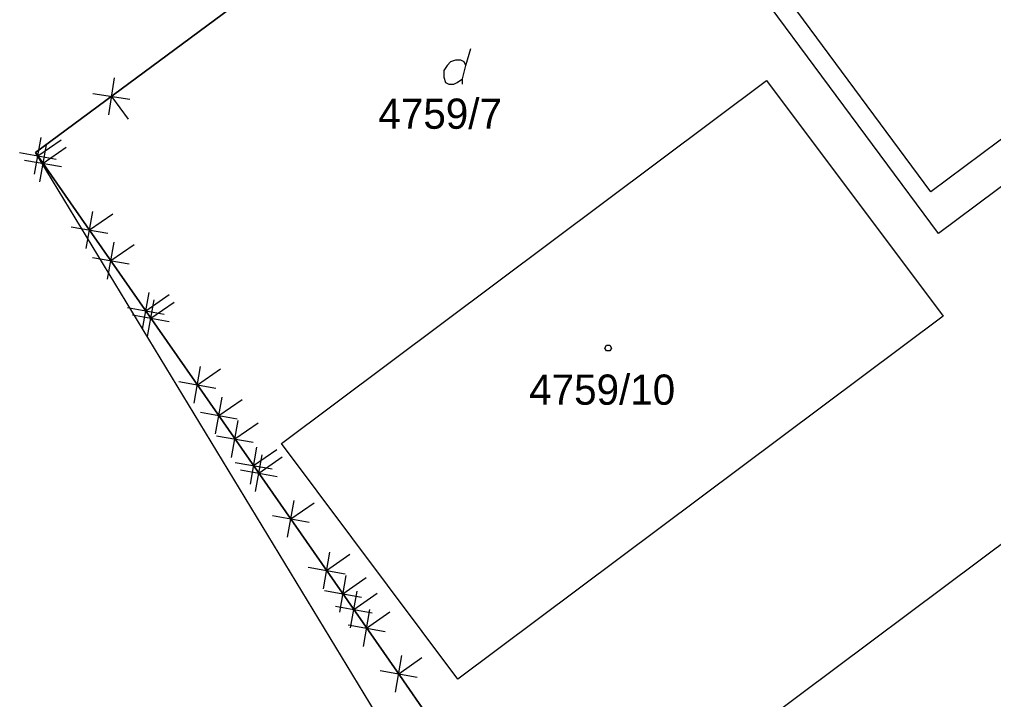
# Model space of a CAD drawing. Extents: x -266179 to -264727, y -1243225 to -1241702.
# Drawn here: x -265653.7 to -265602.1, y -1243026.3 to -1242990.2 of the extents above; entities that cross this region are included whole.
import ezdxf

# ---------------------------------------------------------------- set-up
doc = ezdxf.new("R2010")
doc.units = 0
doc.layers.add('Vrstva 1', color=7, linetype='Continuous')
doc.layers.add('Vrstva 21', color=7, linetype='Continuous')

msp = doc.modelspace()

# ---------------------------------------------------------------- linework, layer by layer
at = {"layer": 'Vrstva 1'}
for p, q in [((-265566.78, -1242970.48), (-265605.43, -1242999.37)), ((-265652.86, -1242997.29), (-265624.02, -1242975.93)), ((-265605.04, -1243001.58), (-265624.02, -1242975.93)), ((-265605.43, -1242999.37), (-265612.83, -1242989.37)), ((-265630.07, -1242992.67), (-265629.8, -1242991.77)), ((-265639.84, -1243012.7), (-265614.14, -1242993.47)), ((-265614.14, -1242993.47), (-265604.79, -1243005.96)), ((-265649.88, -1243001.57), (-265652.86, -1242997.29)), ((-265631.74, -1243032.06), (-265652.86, -1242997.29)), ((-265599.44, -1242997.39), (-265605.04, -1243001.58)), ((-265643.89, -1243010.17), (-265649.88, -1243001.57)), ((-265604.79, -1243005.96), (-265630.5, -1243025.19)), ((-265640.3, -1243015.33), (-265643.89, -1243010.17)), ((-265630.5, -1243025.19), (-265639.84, -1243012.7)), ((-265633.72, -1243024.77), (-265640.3, -1243015.33)), ((-265623.61, -1243034.4), (-265597.9, -1243015.17)), ((-265630.77, -1243029.01), (-265633.72, -1243024.77))]:
    msp.add_line(p, q, dxfattribs=at)
msp.add_lwpolyline([(-265630.25, -1242993.66), (-265630.25, -1242993.39), (-265630.07, -1242992.67), (-265630.16, -1242992.49), (-265630.34, -1242992.4), (-265630.61, -1242992.4), (-265630.88, -1242992.49), (-265631.06, -1242992.67), (-265631.24, -1242992.94), (-265631.24, -1242993.3), (-265631.15, -1242993.57), (-265630.97, -1242993.66), (-265630.7, -1242993.66), (-265630.52, -1242993.57), (-265630.25, -1242993.39)], dxfattribs=at)
msp.add_lwpolyline([(-265622.44, -1243007.5), (-265622.35, -1243007.65), (-265622.44, -1243007.8), (-265622.62, -1243007.8), (-265622.71, -1243007.65), (-265622.62, -1243007.5)], close=True, dxfattribs=at)
at = {"layer": 'Vrstva 21'}
for p, q in [((-265652.86, -1242997.29), (-265624.02, -1242975.93)), ((-265624.02, -1242975.93), (-265652.86, -1242997.29)), ((-265648.697, -1242993.333), (-265648.99, -1242995.291)), ((-265649.823, -1242994.166), (-265647.864, -1242994.459)), ((-265648.843, -1242994.312), (-265647.951, -1242995.518)), ((-265652.912, -1242998.441), (-265652.563, -1242996.492)), ((-265652.737, -1242997.467), (-265651.506, -1242996.61)), ((-265653.711, -1242997.292), (-265651.763, -1242997.641)), ((-265649.88, -1243001.57), (-265652.86, -1242997.29)), ((-265652.86, -1242997.29), (-265649.88, -1243001.57)), ((-265652.637, -1242998.835), (-265652.288, -1242996.886)), ((-265652.462, -1242997.861), (-265651.231, -1242997.004)), ((-265653.437, -1242997.686), (-265651.488, -1242998.035)), ((-265650.177, -1243002.368), (-265649.828, -1243000.419)), ((-265650.003, -1243001.393), (-265648.772, -1243000.536)), ((-265650.977, -1243001.219), (-265649.029, -1243001.568)), ((-265643.89, -1243010.17), (-265649.88, -1243001.57)), ((-265649.88, -1243001.57), (-265643.89, -1243010.17)), ((-265649.043, -1243003.992), (-265648.694, -1243002.043)), ((-265648.868, -1243003.018), (-265647.637, -1243002.161)), ((-265649.843, -1243002.843), (-265647.894, -1243003.192)), ((-265647.196, -1243006.647), (-265646.847, -1243004.698)), ((-265647.022, -1243005.672), (-265645.791, -1243004.815)), ((-265647.996, -1243005.498), (-265646.047, -1243005.847)), ((-265646.923, -1243007.042), (-265646.574, -1243005.093)), ((-265646.748, -1243006.068), (-265645.517, -1243005.211)), ((-265647.723, -1243005.893), (-265645.774, -1243006.242)), ((-265644.464, -1243010.575), (-265644.115, -1243008.626)), ((-265644.289, -1243009.6), (-265643.058, -1243008.743)), ((-265645.263, -1243009.426), (-265643.315, -1243009.775)), ((-265640.3, -1243015.33), (-265643.89, -1243010.17)), ((-265643.89, -1243010.17), (-265640.3, -1243015.33)), ((-265643.329, -1243012.199), (-265642.98, -1243010.25)), ((-265643.154, -1243011.225), (-265641.923, -1243010.368)), ((-265644.129, -1243011.05), (-265642.18, -1243011.399)), ((-265642.473, -1243013.44), (-265642.126, -1243011.491)), ((-265642.299, -1243012.466), (-265641.069, -1243011.607)), ((-265643.274, -1243012.292), (-265641.325, -1243012.639)), ((-265641.482, -1243014.854), (-265641.133, -1243012.905)), ((-265641.308, -1243013.879), (-265640.077, -1243013.022)), ((-265641.21, -1243015.25), (-265640.861, -1243013.301)), ((-265642.282, -1243013.705), (-265640.333, -1243014.054)), ((-265641.036, -1243014.275), (-265639.805, -1243013.418)), ((-265642.01, -1243014.101), (-265640.061, -1243014.45)), ((-265633.72, -1243024.77), (-265640.3, -1243015.33)), ((-265640.3, -1243015.33), (-265633.72, -1243024.77)), ((-265639.513, -1243017.672), (-265639.164, -1243015.724)), ((-265639.338, -1243016.698), (-265638.107, -1243015.841)), ((-265640.313, -1243016.523), (-265638.364, -1243016.872)), ((-265637.616, -1243020.408), (-265637.269, -1243018.459)), ((-265637.443, -1243019.433), (-265636.213, -1243018.575)), ((-265638.417, -1243019.26), (-265636.468, -1243019.607)), ((-265636.751, -1243021.641), (-265636.404, -1243019.692)), ((-265636.577, -1243020.667), (-265635.347, -1243019.808)), ((-265637.552, -1243020.493), (-265635.603, -1243020.84)), ((-265636.173, -1243022.473), (-265635.824, -1243020.524)), ((-265635.999, -1243021.498), (-265634.768, -1243020.641)), ((-265636.973, -1243021.324), (-265635.024, -1243021.673)), ((-265635.496, -1243023.457), (-265635.147, -1243021.508)), ((-265635.322, -1243022.482), (-265634.091, -1243021.625)), ((-265636.296, -1243022.308), (-265634.347, -1243022.657)), ((-265633.799, -1243025.879), (-265633.45, -1243023.93)), ((-265633.624, -1243024.905), (-265632.393, -1243024.048)), ((-265634.599, -1243024.73), (-265632.65, -1243025.079)), ((-265630.77, -1243029.01), (-265633.72, -1243024.77)), ((-265633.72, -1243024.77), (-265630.77, -1243029.01))]:
    msp.add_line(p, q, dxfattribs=at)

# ---------------------------------------------------------------- texts
at = {"layer": 'Vrstva 1'}
for s, p in [('4759/7', (-265634.699, -1242996.03)), ('4759/10', (-265626.713, -1243010.65))]:
    msp.add_text(s, height=1.6, dxfattribs=at).set_placement(p)

doc.saveas('drawing.dxf')
